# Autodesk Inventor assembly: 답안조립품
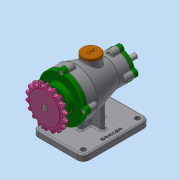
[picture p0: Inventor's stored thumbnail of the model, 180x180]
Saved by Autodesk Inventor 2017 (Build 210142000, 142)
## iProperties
Part Number: 답안조립품
Material: 일반
Document SubType Name: Assembly
Designer: 222
Author: 222
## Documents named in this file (15)
- C:\Users\222\Desktop\701206V1015\답안조립품.iam
- C:\Users\222\Desktop\701206V1015\본체.ipt
- C:\Users\222\Desktop\701206V1015\축.ipt
- C:\Users\222\Desktop\701206V1015\키 4x4x14.ipt
- C:\Users\222\Desktop\701206V1015\베어링 6203.ipt
- C:\Users\222\Desktop\701206V1015\앞커버.ipt
- C:\Users\222\Desktop\701206V1015\오일 실 17 30 8.ipt
- C:\Users\222\Desktop\701206V1015\볼트 M5.ipt
- C:\Users\222\Desktop\701206V1015\스프로킷.ipt
- C:\Users\222\Desktop\701206V1015\뒤커버.ipt
- C:\Users\222\Desktop\701206V1015\베어링 6200.ipt
- C:\Users\222\Desktop\701206V1015\오일 실 10 20 7.ipt
- C:\Users\222\Desktop\701206V1015\개스킷 B.ipt
- C:\Users\222\Desktop\701206V1015\개스킷 A.ipt
- C:\Users\222\Desktop\701206V1015\마개.ipt
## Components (2 placed, 2 different names)
1. 개스킷 B:1
2. 개스킷 A:1
